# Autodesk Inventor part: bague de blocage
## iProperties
Shininess: 64.0
Length Units: 11269
Angle Units: 11279
Time Units: 11290
Mass Units: 11283
Length Display Precision: 3
Angle Display Precision: 2
Compacted: True
Part Number: bague de blocage
Document SubType Name: Modeling
Created: 2004-12
Material: Par défaut
Designer: LEGERET Philippe
Density: 0.0
Volumn: 0.0
Area: 0.0
PropertySet Name: Model Information
Control State: 0
Master: False
Checked Out: False
Author: LEGERET Philippe
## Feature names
1. Extrusion1
2. Perçage1 [Hole]
3. Extrusion2
4. Extrusion3
5. Perçage2 [Hole]
6. Perçage3 [Hole]
